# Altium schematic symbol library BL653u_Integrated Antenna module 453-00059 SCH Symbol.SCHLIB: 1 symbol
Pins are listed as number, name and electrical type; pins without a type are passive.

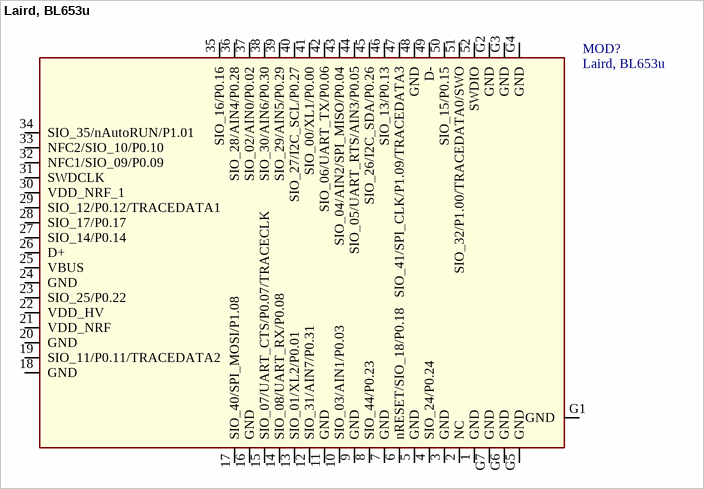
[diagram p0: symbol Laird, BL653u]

## Laird, BL653u
designator MOD?
BL653µ Integrated Antenna module, 453-00059; Substitutes Allowed: NO
pins: 1 GND, 2 NC, 3 GND, 4 SIO_24/P0.24, 5 GND, 6 nRESET/SIO_18/P0.18, 7 GND, 8 SIO_44/P0.23, 9 GND, 10 SIO_03/AIN1/P0.03, 11 GND, 12 SIO_31/AIN7/P0.31, 13 SIO_01/XL2/P0.01, 14 SIO_08/UART_RX/P0.08, 15 SIO_07/UART_CTS/P0.07/TRACECLK, 16 GND, 17 SIO_40/SPI_MOSI/P1.08, 18 GND, 19 SIO_11/P0.11/TRACEDATA2, 20 GND, 21 VDD_NRF, 22 VDD_HV, 23 SIO_25/P0.22           , 24 GND, 25 VBUS, 26 D+, 27 SIO_14/P0.14, 28 SIO_17/P0.17, 29 SIO_12/P0.12/TRACEDATA1, 30 VDD_NRF_1, 31 SWDCLK, 32 NFC1/SIO_09/P0.09, 33 NFC2/SIO_10/P0.10, 34 SIO_35/nAutoRUN/P1.01, 35 SIO_16/P0.16, 36 SIO_28/AIN4/P0.28, 37 SIO_02/AIN0/P0.02, 38 SIO_30/AIN6/P0.30, 39 SIO_29/AIN5/P0.29, 40 SIO_27/I2C_SCL/P0.27, 41 SIO_00/XL1/P0.00, 42 SIO_06/UART_TX/P0.06, 43 SIO_04/AIN2/SPI_MISO/P0.04, 44 SIO_05/UART_RTS/AIN3/P0.05, 45 SIO_26/I2C_SDA/P0.26, 46 SIO_13/P0.13, 47 SIO_41/SPI_CLK/P1.09/TRACEDATA3, 48 GND, 49 D-, 50 SIO_15/P0.15, 51 SIO_32/P1.00/TRACEDATA0/SWO, 52 SWDIO, G1 GND, G2 GND, G3 GND, G4 GND, G5 GND, G6 GND, G7 GND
